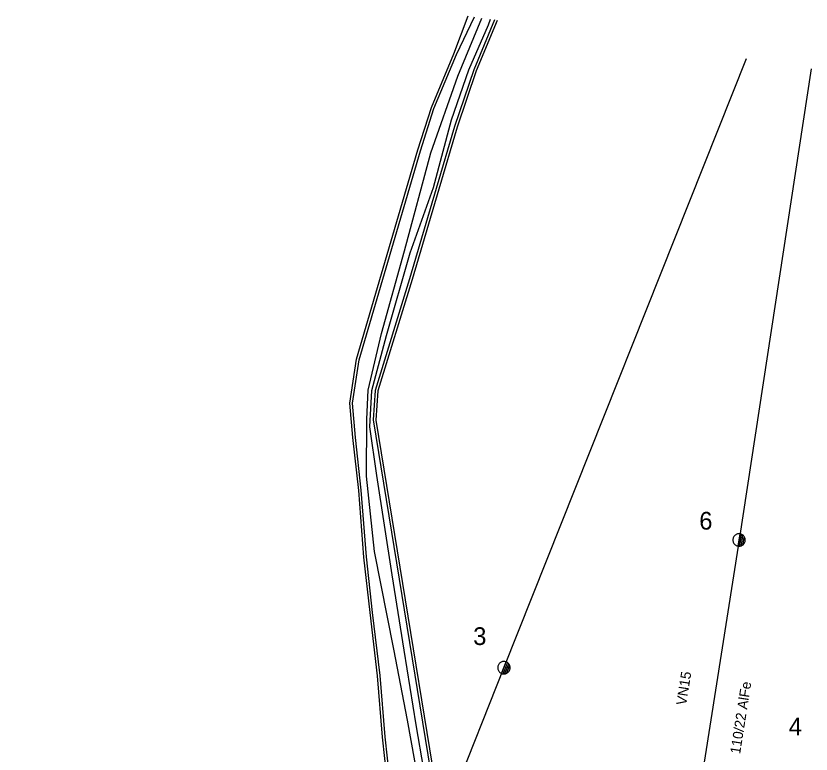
# Model space of a CAD drawing. Extents: x -540340 to -537226, y -1183949 to -1180375.
# Drawn here: x -537503.3 to -537424.8, y -1180548.7 to -1180475.7 of the extents above; entities that cross this region are included whole.
import ezdxf

# ---------------------------------------------------------------- set-up
doc = ezdxf.new("R2010")
doc.units = 0
for name, color, linetype in [('Vrstva 1', 7, 'Continuous'), ('Vrstva 13', 7, 'Continuous'), ('Vrstva 14', 7, 'Continuous'), ('Vrstva 2', 7, 'Continuous'), ('Vrstva 3', 7, 'Continuous'), ('Vrstva 5', 7, 'Continuous')]:
    doc.layers.add(name, color=color, linetype=linetype)

msp = doc.modelspace()

# ---------------------------------------------------------------- linework, layer by layer
at = {"layer": 'Vrstva 1'}
for points in [[(-537431.228, -1180479.977), (-537455.152, -1180540.114), (-537475.319, -1180590.928), (-537503.346, -1180635.787)], [(-537424.819, -1180480.966), (-537431.93, -1180527.5), (-537437.05, -1180560.12)]]:
    msp.add_lwpolyline(points, dxfattribs=at)
at = {"layer": 'Vrstva 13'}
for points in [[(-537431.834, -1180526.899), (-537431.898, -1180526.892), (-537431.962, -1180526.893), (-537432.026, -1180526.899), (-537432.089, -1180526.913), (-537432.15, -1180526.933), (-537432.209, -1180526.959), (-537432.264, -1180526.991), (-537432.316, -1180527.029), (-537432.364, -1180527.072), (-537432.407, -1180527.12), (-537432.445, -1180527.172), (-537432.477, -1180527.228), (-537432.503, -1180527.287), (-537432.523, -1180527.348), (-537432.536, -1180527.411), (-537432.543, -1180527.474), (-537432.542, -1180527.539), (-537432.536, -1180527.603), (-537432.522, -1180527.665), (-537432.502, -1180527.727), (-537432.476, -1180527.785), (-537432.444, -1180527.841), (-537432.406, -1180527.893), (-537432.363, -1180527.941), (-537432.315, -1180527.983), (-537432.263, -1180528.021), (-537432.207, -1180528.053), (-537432.148, -1180528.08), (-537432.087, -1180528.099), (-537432.024, -1180528.113), (-537431.96, -1180528.119), (-537431.896, -1180528.119), (-537431.832, -1180528.112), (-537431.769, -1180528.099), (-537431.708, -1180528.079), (-537431.65, -1180528.053), (-537431.594, -1180528.02), (-537431.542, -1180527.983), (-537431.494, -1180527.939), (-537431.451, -1180527.892), (-537431.414, -1180527.839), (-537431.382, -1180527.784), (-537431.355, -1180527.725), (-537431.336, -1180527.664), (-537431.322, -1180527.601), (-537431.316, -1180527.537), (-537431.316, -1180527.473), (-537431.323, -1180527.409), (-537431.336, -1180527.346), (-537431.356, -1180527.285), (-537431.382, -1180527.226), (-537431.415, -1180527.17), (-537431.452, -1180527.119), (-537431.496, -1180527.071), (-537431.543, -1180527.028), (-537431.595, -1180526.99), (-537431.651, -1180526.958), (-537431.71, -1180526.932), (-537431.771, -1180526.912), (-537431.834, -1180526.899)], [(-537432.028, -1180528.114), (-537431.838, -1180526.9)], [(-537431.854, -1180528.112), (-537431.676, -1180526.984)], [(-537431.698, -1180528.049), (-537431.545, -1180527.073)], [(-537431.535, -1180527.938), (-537431.425, -1180527.237)], [(-537454.927, -1180539.549), (-537454.988, -1180539.529), (-537455.05, -1180539.515), (-537455.114, -1180539.507), (-537455.179, -1180539.507), (-537455.242, -1180539.513), (-537455.305, -1180539.525), (-537455.367, -1180539.545), (-537455.426, -1180539.57), (-537455.482, -1180539.601), (-537455.534, -1180539.639), (-537455.583, -1180539.681), (-537455.626, -1180539.728), (-537455.664, -1180539.78), (-537455.697, -1180539.835), (-537455.724, -1180539.894), (-537455.745, -1180539.955), (-537455.759, -1180540.017), (-537455.766, -1180540.081), (-537455.767, -1180540.145), (-537455.761, -1180540.21), (-537455.748, -1180540.273), (-537455.729, -1180540.334), (-537455.703, -1180540.393), (-537455.672, -1180540.449), (-537455.635, -1180540.501), (-537455.592, -1180540.55), (-537455.545, -1180540.593), (-537455.493, -1180540.632), (-537455.438, -1180540.664), (-537455.38, -1180540.691), (-537455.319, -1180540.712), (-537455.256, -1180540.726), (-537455.192, -1180540.733), (-537455.128, -1180540.734), (-537455.064, -1180540.728), (-537455.001, -1180540.715), (-537454.939, -1180540.696), (-537454.88, -1180540.671), (-537454.824, -1180540.639), (-537454.772, -1180540.602), (-537454.724, -1180540.559), (-537454.68, -1180540.512), (-537454.642, -1180540.46), (-537454.609, -1180540.405), (-537454.582, -1180540.347), (-537454.562, -1180540.286), (-537454.548, -1180540.223), (-537454.54, -1180540.159), (-537454.539, -1180540.095), (-537454.545, -1180540.031), (-537454.558, -1180539.968), (-537454.577, -1180539.906), (-537454.603, -1180539.848), (-537454.634, -1180539.792), (-537454.672, -1180539.739), (-537454.714, -1180539.691), (-537454.761, -1180539.647), (-537454.813, -1180539.609), (-537454.868, -1180539.576), (-537454.927, -1180539.549)], [(-537455.384, -1180540.691), (-537454.931, -1180539.55)], [(-537455.213, -1180540.728), (-537454.792, -1180539.667)], [(-537455.047, -1180540.701), (-537454.683, -1180539.782)], [(-537454.864, -1180540.629), (-537454.602, -1180539.969)]]:
    msp.add_lwpolyline(points, dxfattribs=at)
at = {"layer": 'Vrstva 5'}
for points in [[(-537466.675, -1180551.194), (-537467.134, -1180546.985), (-537467.637, -1180540.932), (-537468.378, -1180534.685), (-537468.975, -1180529.19), (-537469.495, -1180522.619), (-537470.072, -1180517.395), (-537470.354, -1180513.989), (-537469.702, -1180509.647), (-537463.643, -1180488.985), (-537462.294, -1180484.786), (-537460.083, -1180479.477), (-537458.669, -1180475.741)], [(-537466.426, -1180551.171), (-537466.885, -1180546.961), (-537467.388, -1180540.907), (-537468.13, -1180534.657), (-537468.726, -1180529.167), (-537469.246, -1180522.595), (-537469.823, -1180517.371), (-537470.102, -1180513.997), (-537469.457, -1180509.701), (-537463.404, -1180489.058), (-537462.059, -1180484.872), (-537459.851, -1180479.569), (-537458.051, -1180475.837)], [(-537462.946, -1180554.989), (-537464.683, -1180545.299), (-537466.034, -1180538.293), (-537467.943, -1180528.657), (-537468.728, -1180521.212), (-537468.68, -1180515.579), (-537468.556, -1180512.699), (-537467.254, -1180507.128), (-537464.959, -1180498.941), (-537462.367, -1180489.277), (-537459.704, -1180481.709), (-537457.321, -1180475.949)], [(-537462.321, -1180554.578), (-537463.81, -1180545.749), (-537465.013, -1180538.393), (-537466.19, -1180530.957), (-537467.708, -1180521.154), (-537468.381, -1180516.325), (-537468.193, -1180512.756), (-537466.735, -1180507.296), (-537464.426, -1180499.134), (-537462.099, -1180492.684), (-537460.338, -1180486.017), (-537458.609, -1180481.064), (-537456.67, -1180476.614), (-537456.475, -1180476.08)], [(-537456.072, -1180476.142), (-537458.135, -1180481.065), (-537460.019, -1180486.661), (-537461.835, -1180492.784), (-537464.466, -1180501.7), (-537467.857, -1180512.745), (-537468.066, -1180515.655), (-537459.602, -1180567.509)], [(-537455.818, -1180476.181), (-537457.901, -1180481.153), (-537459.781, -1180486.736), (-537461.595, -1180492.855), (-537464.227, -1180501.772), (-537467.61, -1180512.791), (-537467.817, -1180515.673), (-537459.353, -1180567.48)]]:
    msp.add_lwpolyline(points, dxfattribs=at)

# ---------------------------------------------------------------- texts
at = {"layer": 'Vrstva 14'}
for s, p in [('6', (-537435.862, -1180526.482)), ('3', (-537458.184, -1180537.88)), ('4', (-537427.028, -1180546.801))]:
    msp.add_text(s, height=1.75, dxfattribs=at).set_placement(p)
at = {"layer": 'Vrstva 2'}
msp.add_text('110/22 AlFe', height=1, rotation=81.08, dxfattribs=at).set_placement((-537431.832, -1180548.698))
at = {"layer": 'Vrstva 3'}
msp.add_text('VN15', height=1, rotation=81.08, dxfattribs=at).set_placement((-537437.159, -1180543.885))

doc.saveas('drawing.dxf')
